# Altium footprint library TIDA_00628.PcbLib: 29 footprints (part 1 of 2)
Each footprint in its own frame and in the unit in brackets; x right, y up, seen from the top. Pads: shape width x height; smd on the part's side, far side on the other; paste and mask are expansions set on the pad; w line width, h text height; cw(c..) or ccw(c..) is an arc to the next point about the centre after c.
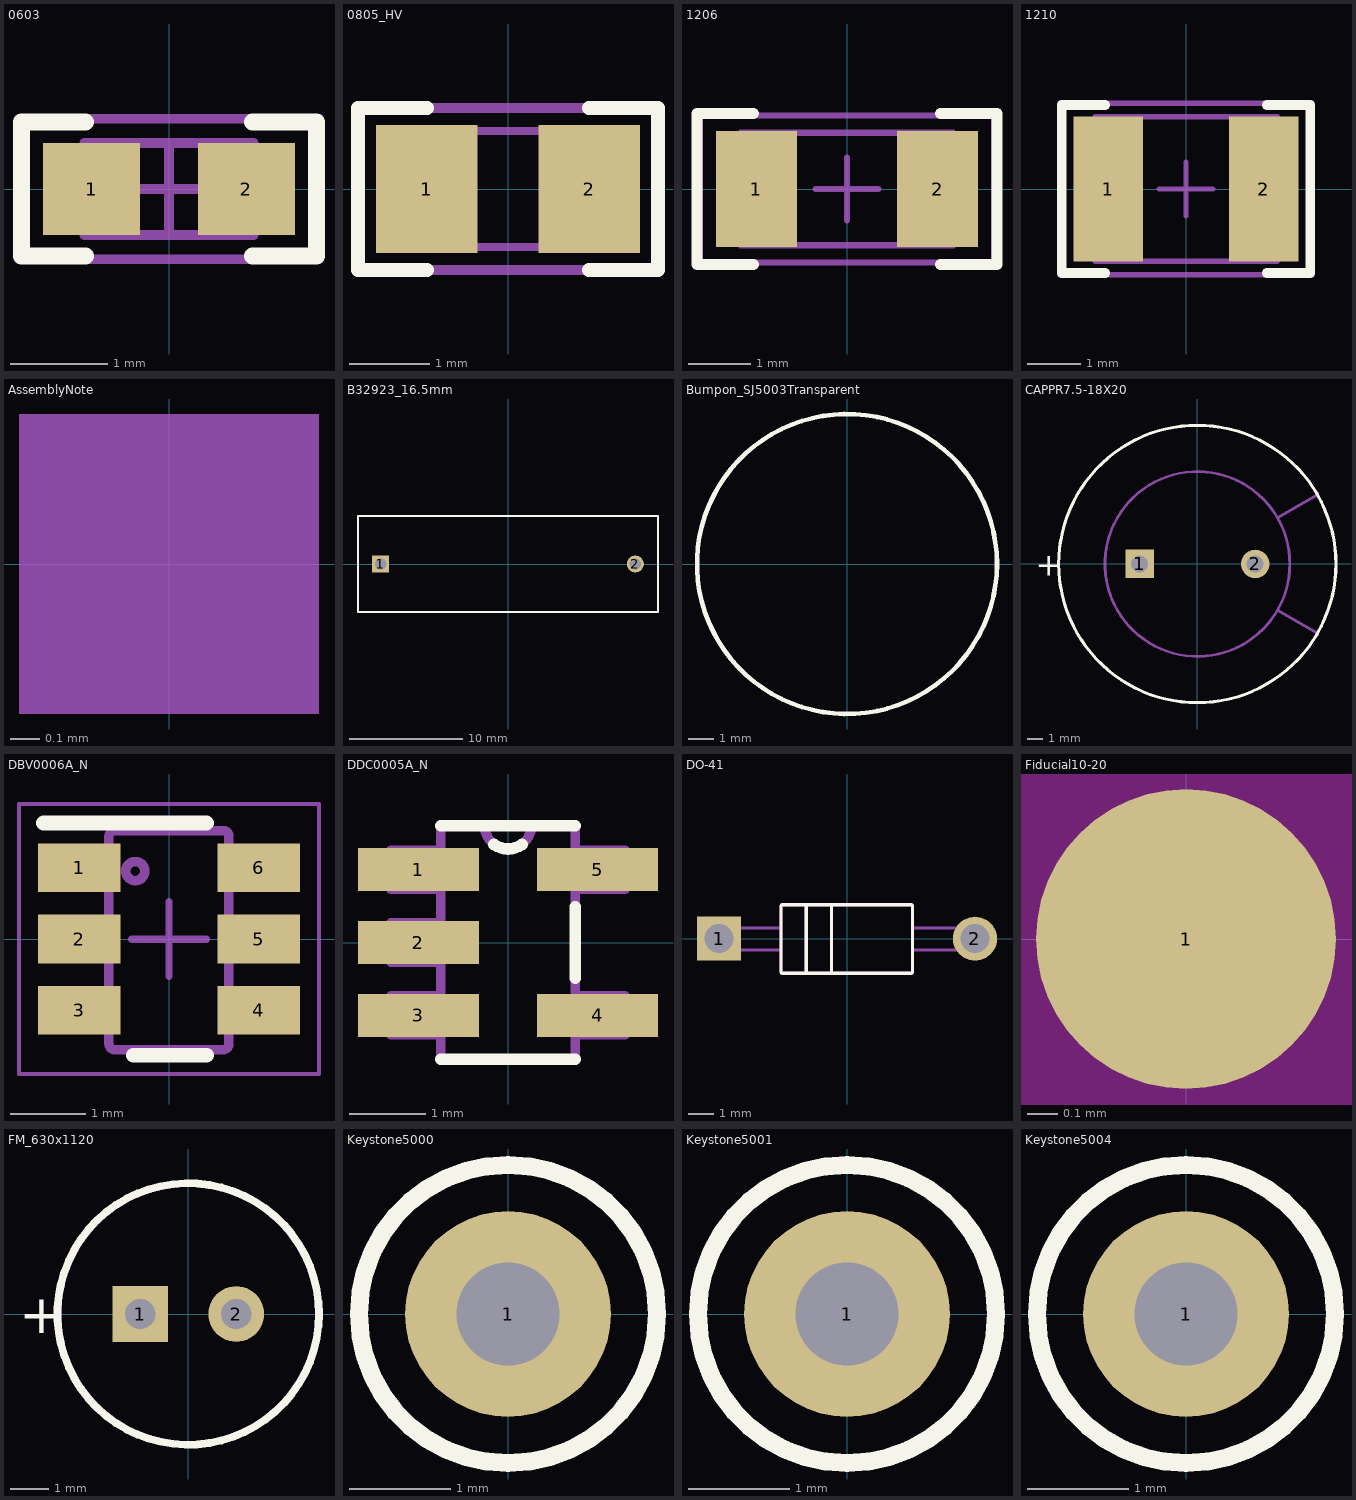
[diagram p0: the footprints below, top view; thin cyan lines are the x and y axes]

## 0603 [mm] "0603 from SM-752 data"
height 0.85
pads (2):
  rect 1x0.95 smd: 1(-0.8,0) 2(0.8,0)
Top Overlay:
  lines w0.178: -0.864,-0.691 -1.524,-0.691 -1.524,0.693 -0.864,0.693 ; 0.864,-0.691 1.524,-0.691 1.524,0.693 0.864,0.693
Mechanical 5:
  lines w0.1: -1.55,-0.725 -1.55,0.725 1.55,0.725 1.55,-0.725 -1.55,-0.725
  text ".Designator" at -1.397,-0.381 h0.76
Mechanical 13:
  lines w0.1: -0.55,-0.475 -0.55,0.475 ; 0.55,-0.475 0.55,0.475 ; -0.875,-0.475 0.875,-0.475 0.875,0.475 -0.875,0.475 -0.875,-0.475
Mechanical 15:
  lines w0.1: -0.475,0 0.475,0 ; 0,-0.475 0,0.475 ; -1.55,-0.725 1.55,-0.725 1.55,0.725 -1.55,0.725 -1.55,-0.725
3D body: height 0.85, standoff 0, extent -0.874,-0.474 -0.551,0.474
3D body: height 0.85, standoff 0, extent -0.549,-0.474 0.549,0.474
3D body: height 0.85, standoff 0, extent 0.551,-0.474 0.874,0.474

## 0805_HV [mil] "0805 with 30mil clearance between pads"
height 43.31
pads (2):
  rect 50x63 smd: 1(-40,0) 2(40,0)
Top Overlay:
  lines w7: -40,-40 -74,-40 -74,0 -74,40 -40,40 ; 40,-40 74,-40 74,0 74,40 40,40
Mechanical 5:
  lines w5: -74,-40 -74,40 74,40 74,-40 -74,-40
  text ".Designator" at -64,-17 h35
Mechanical 13:
  lines w3.94: -25.59,-28.54 -25.59,28.54 ; 25.59,-28.54 25.59,28.54 ; -43.31,-28.54 43.31,-28.54 43.31,28.54 -43.31,28.54 -43.31,-28.54
3D body: height 43.31, standoff 0, extent -43.29,-28.52 -25.61,28.52
3D body: height 43.31, standoff 0, extent -25.57,-28.52 25.57,28.52
3D body: height 43.31, standoff 0, extent 25.61,-28.52 43.29,28.52

## 1206 [mm] "1206 from SM-752 data"
height 1.35
pads (2):
  rect 1.3x1.85 smd: 1(-1.45,0) 2(1.45,0)
Top Overlay:
  lines w0.178: -1.5,-1.21 -2.4,-1.21 -2.4,1.21 -1.5,1.21 ; 1.5,-1.21 2.4,-1.21 2.4,1.21 1.5,1.21
Mechanical 5:
  lines w0.1: -1.7,-0.9 -1.7,0.9 1.7,0.9 1.7,-0.9 -1.7,-0.9
  text ".Designator" at -1.475,-0.4 h0.81
Mechanical 13:
  lines w0.1: -1.2,-0.9 -1.2,0.9 ; 1.2,-0.9 1.2,0.9 ; -1.7,-0.9 -1.7,0.9 1.7,0.9 1.7,-0.9 -1.7,-0.9
Mechanical 15:
  lines w0.1: -0.5,0 0.5,0 ; 0,-0.5 0,0.5 ; -2.35,-1.175 -2.35,1.175 2.35,1.175 2.35,-1.175 -2.35,-1.175
3D body: height 1.35, standoff 0, extent 1.201,-0.899 1.699,0.899
3D body: height 1.35, standoff 0, extent -1.199,-0.899 1.199,0.899
3D body: height 1.35, standoff 0, extent -1.699,-0.899 -1.201,0.899

## 1210 [mm] "1210 from SM-752 data"
height 1.35
pads (2):
  rect 1.3x2.7 smd: 1(-1.45,0) 2(1.45,0)
Top Overlay:
  lines w0.178: -1.511,-1.568 -2.316,-1.568 -2.316,1.568 -1.511,1.568 ; 1.511,-1.568 2.316,-1.568 2.316,1.568 1.511,1.568
Mechanical 5:
  lines w0.1: -1.7,-1.35 1.7,-1.35 1.7,1.35 -1.7,1.35 -1.7,-1.35
  text ".Designator" at -1.4,-0.375 h0.76
Mechanical 13:
  lines w0.1: -1.2,-1.35 -1.2,1.35 ; 1.2,-1.35 1.2,1.35 ; -1.7,-1.35 -1.7,1.35 1.7,1.35 1.7,-1.35 -1.7,-1.35
Mechanical 15:
  lines w0.1: -0.5,0 0.5,0 ; 0,-0.5 0,0.5 ; -2.35,-1.6 -2.35,1.6 2.35,1.6 2.35,-1.6 -2.35,-1.6
3D body: height 1.35, standoff 0, extent -1.699,-1.349 -1.201,1.349
3D body: height 1.35, standoff 0, extent -1.199,-1.349 1.199,1.349
3D body: height 1.35, standoff 0, extent 1.201,-1.349 1.699,1.349

## AssemblyNote [mm] "Assembly Note"
Mechanical 5:
  rectangle: -0.508,-0.508 0.508,0.508
  text ".Designator" at -4.191,-0.508 h1.02
  text ".Comment" at 1.143,-0.508 h1.02

## B32923_16.5mm [mm] "Epcos film capacitors, 22.5mm spacing"
height 16.5
pads (2):
  rect 1.5x1.5 hole 1: 1(-11.25,0)
  round 1.5 hole 1: 2(11.25,0)
Top Overlay:
  lines w0.178: -13.25,-4.25 0,-4.25 13.25,-4.25 13.25,0 13.25,4.25 0,4.25 -13.25,4.25 -13.25,0 -13.25,-4.25
Mechanical 5:
  lines w0.127: -13.25,-4.25 -13.25,0 -13.25,4.25 0,4.25 13.25,4.25 13.25,0 13.25,-4.25 0,-4.25 -13.25,-4.25
  text ".Designator" at -1.524,-0.508 h1.02
3D body: height 16.5, standoff 0, extent -13.249,-4.249 13.249,4.249

## Bumpon_SJ5003Transparent [mil] "3M Hemispherical Bumpon transparent"
height 200
pads (1):
  round 1 on Mech3: 0(0,0)
Top Overlay:
  circle w7: c0,0 r228.04
Mechanical 5:
  circle w5: c0,0 r228.04
  text ".Designator" at -60,-20 h40
3D body: height 196.82, standoff 0, extent -216.78,-218.07 218.51,218.08

## CAPPR7.5-18X20 [mm] "Capacitor, Electrolytic, Radial; Body 18 x 20 mm (Dia.xH typ); Pin Spacing 7.5 mm (typ)"
height 22
pads (2):
  rect 1.85x1.85 hole 1.1: 1(-3.75,0)
  round 1.85 hole 1.1: 2(3.75,0)
Top Overlay:
  circle w0.2: c-0.004,-0.001 r9
  text "+" at -10.475,-0.75 h1.5
Mechanical 5:
  circle w0.127: c-0.004,-0.001 r9
  text "+" at -10.475,-0.75 h1.5
  text ".Designator" at -1.524,-0.508 h1.02
Mechanical 13:
  circle w0.178: c3.75,0 r0.4
  circle w0.178: c-3.75,0 r0.4
  circle w0.178: c0,0 r6
  lines w0.178: 5.196,-3 7.794,-4.5 ; 5.196,3 7.794,4.5
3D body: height 1, standoff -2.54, extent 3.343,-0.407 4.157,0.407
3D body: height 1, standoff -2.54, extent -4.157,-0.407 -3.343,0.407
3D body: height 22, standoff 0, extent -6.01,-6.01 7.795,6.01
3D body: height 22, standoff 0, extent -9.01,-9.01 7.795,9.01
3D body: height 22, standoff 0, extent 5.196,-4.501 9.011,4.501

## DBV0006A_N [mm] "SOT23, 6-Leads, Body 2.9x1.6mm, Pitch 0.95mm, Lead Span 2.8mm, IPC Medium Density"
height 1.45
pads (6):
  rect 1.1x0.65 smd: 1(-1.2,0.95) 2(-1.2,0) 3(-1.2,-0.95) 4(1.2,-0.95) 5(1.2,0) 6(1.2,0.95)
Top Overlay:
  lines w0.2: -1.675,1.55 0.5,1.55 ; -0.475,-1.55 0.5,-1.55
Mechanical 5:
  lines w0.127: 0.724,-1.475 ccw(c0.723,-1.399) 0.8,-1.399 0.8,1.37 ccw(c0.723,1.37) 0.724,1.446 ; 0.723,-1.475 0.724,-1.475 ; 0.723,-1.475 -0.724,-1.475 -0.725,-1.475 cw(c-0.724,-1.399) -0.801,-1.399 -0.801,1.37 cw(c-0.724,1.37) -0.725,1.446 -0.724,1.446 0.723,1.446 ; 0.723,1.446 0.724,1.446 ; -1.423,-1.154 -1.206,-1.154 -1.113,-1.154 -1.081,-1.154 -0.828,-1.154 -0.801,-1.154 -0.801,-0.78 -0.828,-0.78 -1.081,-0.78 -1.113,-0.78 -1.206,-0.78 -1.423,-0.78 -1.423,-1.154 ; -1.423,-0.202 -1.206,-0.202 -1.113,-0.202 -1.081,-0.202 -0.828,-0.202 -0.801,-0.202 -0.801,0.173 -0.828,0.173 -1.081,0.173 -1.113,0.173 -1.206,0.173 -1.423,0.173 -1.423,-0.202 ; -1.423,0.751 -1.206,0.751 -1.113,0.751 -1.081,0.751 -0.828,0.751 -0.801,0.751 -0.801,1.125 -0.828,1.125 -1.081,1.125 -1.113,1.125 -1.206,1.125 -1.423,1.125 -1.423,0.751 ; -0.577,0.906 cw(c-0.45,0.906) -0.323,0.906 cw(c-0.45,0.906) -0.577,0.906 ; 0.8,-1.154 0.827,-1.154 1.08,-1.154 1.112,-1.154 1.205,-1.154 1.422,-1.154 1.422,-0.78 1.205,-0.78 1.112,-0.78 1.08,-0.78 0.827,-0.78 0.8,-0.78 0.8,-1.154 ; 0.8,-0.202 0.827,-0.202 1.08,-0.202 1.112,-0.202 1.205,-0.202 1.422,-0.202 1.422,0.173 1.205,0.173 1.112,0.173 1.08,0.173 0.827,0.173 0.8,0.173 0.8,-0.202 ; 0.8,0.751 0.827,0.751 1.08,0.751 1.112,0.751 1.205,0.751 1.422,0.751 1.422,1.125 1.205,1.125 1.112,1.125 1.08,1.125 0.827,1.125 0.8,1.125 0.8,0.751
  text ".Designator" at -0.075,0.925 h0.51
Mechanical 15:
  lines w0.05: -2,-1.8 -2,1.8 2,1.8 2,-1.8 -2,-1.8
  lines w0.1: -0.5,0 0.5,0 ; 0,-0.5 0,0.5
3D body: height 1.11, standoff -0.01, extent -1.422,-1.461 1.422,1.46

## DDC0005A_N [mil]
height 43.31
pads (5):
  rect 62x22 smd: 1(-46,37.4) 2(-46,0) 3(-46,-37.4) 4(46,-37.4) 5(46,37.4)
Top Overlay:
  lines w6: -34.5,-60 34.5,-60 ; -34.5,60 34.5,60 ; -7.14,50.35 ccw(c0,60) 7.14,50.35 ; 34.5,-18.3 34.5,18.3
Mechanical 5:
  lines w5: -12,60 ccw(c0,60) 12,60 ; -60,-47.4 -60,-27.4 -34.5,-27.4 -34.5,-47.4 -60,-47.4 ; -60,-10 -60,10 -34.5,10 -34.5,-10 -60,-10 ; -60,27.4 -60,47.4 -34.5,47.4 -34.5,27.4 -60,27.4 ; -34.5,-60 34.5,-60 34.5,60 -34.5,60 -34.5,-60 ; 34.5,-47.4 34.5,-27.4 60,-27.4 60,-47.4 34.5,-47.4 ; 34.5,27.4 34.5,47.4 60,47.4 60,27.4 34.5,27.4
  text ".Designator" at -70,-20 h40
3D body: height 23.62, standoff 0, extent -59.98,-47.38 -34.52,-27.42
3D body: height 23.62, standoff 0, extent -59.98,27.42 -34.52,47.38
3D body: height 23.62, standoff 0, extent 34.52,-47.38 59.98,-27.42
3D body: height 23.62, standoff 0, extent 34.52,27.42 59.98,47.38
3D body: height 23.62, standoff 0, extent -59.98,-9.98 -34.52,9.98
3D body: height 43.31, standoff 0, extent -34.48,-59.98 34.48,59.98
3D body: height 43.31, standoff 0, extent -34.5,47.74 34.52,60.02

## DO-41 [mm] "diode"
height 3
pads (2):
  rect 1.75x1.75 hole 1.15: 1(-5.08,0)
  round 1.75 hole 1.15: 2(5.08,0)
Top Overlay:
  lines w0.127: -1.615,-1.371 -0.615,-1.371 ; -1.615,1.347 -0.615,1.347 ; -2.615,-1.322 ccw(c-2.565,-1.322) -2.565,-1.372 -1.615,-1.372 -1.615,-0.012 -1.615,1.348 -2.565,1.348 ccw(c-2.565,1.298) -2.615,1.298 -2.615,-0.012 -2.615,-1.322 ; -0.615,-1.372 2.545,-1.372 ccw(c2.545,-1.322) 2.595,-1.322 2.595,1.298 ccw(c2.545,1.298) 2.545,1.348 -0.615,1.348 -0.615,-1.372
Mechanical 5:
  lines w0.127: -2.615,-0.444 -4.09,-0.444 -5.09,-0.444 cw(c-5.09,-0.012) -5.522,-0.012 cw(c-5.09,-0.012) -5.09,0.42 -4.09,0.42 -2.615,0.42 ; -1.615,-1.371 -0.615,-1.371 ; -1.615,1.347 -0.615,1.347 ; 2.595,-0.444 4.07,-0.444 5.07,-0.444 ccw(c5.07,-0.012) 5.502,-0.012 ccw(c5.07,-0.012) 5.07,0.42 4.07,0.42 2.595,0.42 ; -2.615,-1.322 ccw(c-2.565,-1.322) -2.565,-1.372 -1.615,-1.372 -1.615,-0.012 -1.615,1.348 -2.565,1.348 ccw(c-2.565,1.298) -2.615,1.298 -2.615,-0.012 -2.615,-1.322 ; -0.615,-1.372 -0.615,1.348 2.545,1.348 cw(c2.545,1.298) 2.595,1.298 2.595,-1.322 cw(c2.545,-1.322) 2.545,-1.372 -0.615,-1.372
  text ".Designator" at -0.178,-0.254 h0.51
3D body: height 2.72, standoff -2.6, extent -5.512,-1.36 5.512,1.36

## Fiducial10-20 [mm]
pads (1):
  round 1 smd mask+0.5: 1(0,0)
Top Layer keep-out:
  circle w1.178: c0,0 r0.5

## FM_630x1120 [mm] "PANASONIC"
height 12.7
pads (2):
  rect 1.45x1.45 hole 0.787: 1(-1.25,0)
  round 1.45 hole 0.787: 2(1.25,0)
Top Overlay:
  circle w0.2: c0,0 r3.401
  text "+" at -4.4,-0.5 h1.02
Mechanical 5:
  circle w0.1: c0,0 r3.35
  text "+" at -4.4,-0.5 h1.02
  text ".Designator" at -1.8,-0.4 h1.02
3D body: height 12.71, standoff -4, extent -3.373,-3.394 3.397,3.395

## Keystone5000 [mil] "For Keystone 500x miniature loop terminals"
height 181.1
pads (1):
  round 80 hole 40: 1(0,0)
Top Overlay:
  circle w7: c0,0 r58
Mechanical 5:
  circle w5: c0,0 r58.31
  text ".Designator" at -45,-10 h30
3D body: height 181.97, standoff -118.11, extent -49,-49 49.04,49.24

## Keystone5001 [mil] "For Keystone 500x miniature loop terminals"
height 181.1
pads (1):
  round 80 hole 40: 1(0,0)
Top Overlay:
  circle w7: c0,0 r58
Mechanical 5:
  circle w5: c0,0 r58.31
  text ".Designator" at -45,-10 h30
3D body: height 181.97, standoff -118.11, extent -49,-49 49.04,49.24

## Keystone5004 [mil] "For Keystone 500x miniature loop terminals"
height 181.1
pads (1):
  round 80 hole 40: 1(0,0)
Top Overlay:
  circle w7: c0,0 r58
Mechanical 5:
  circle w5: c0,0 r58.31
  text ".Designator" at -45,-10 h30
3D body: height 181.97, standoff -118.11, extent -49,-49 49.04,49.24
